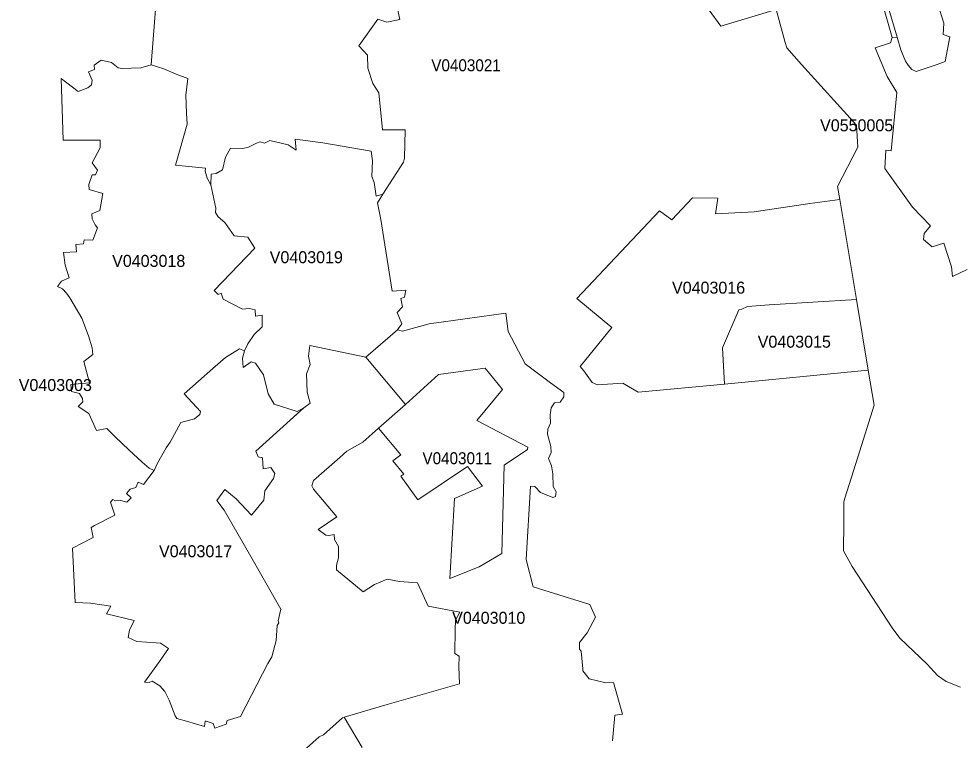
# Model space of a CAD drawing. Extents: x 369010 to 735936, y 6377141 to 6616555.
# Drawn here: x 425432 to 433279, y 6484437 to 6490450 of the extents above; entities that cross this region are included whole.
import ezdxf
from ezdxf.enums import TextEntityAlignment as Align

# ---------------------------------------------------------------- set-up
doc = ezdxf.new("R2010")
doc.units = 0
doc.header["$LTSCALE"] = 40
doc.layers.add('3', color=7, linetype='Continuous', lineweight=13)
doc.layers.add('4', color=7, linetype='Continuous')

msp = doc.modelspace()

# ---------------------------------------------------------------- linework, layer by layer
at = {"layer": '3'}
for points in [[(426643.33, 6491458.57), (426533.77, 6490066.35), (426639.19, 6490033.91), (426743.96, 6489988.9), (426840.12, 6489952.65), (426823.73, 6489813.79), (426829.36, 6489664.18), (426835.98, 6489571.83), (426736.84, 6489230.72), (426987.91, 6489205.07), (426984.27, 6489179.75), (427002.48, 6489120.83), (427031.44, 6489066.87), (427035.74, 6489155.42), (427077.62, 6489159.89), (427128.59, 6489192.16), (427153.91, 6489297.92), (427196.94, 6489370.74), (427300.05, 6489369.41), (427346.72, 6489379.18), (427412.6, 6489412.78), (427443.21, 6489424.53), (427478.8, 6489412.11), (427522.66, 6489436.11), (427675.91, 6489399.54), (427744.1, 6489355.18), (427736.32, 6489445.88), (427965.38, 6489415.59), (428368.22, 6489346.41), (428378.97, 6489265.64), (428374.34, 6489134.73), (428392.54, 6489085.91), (428410.75, 6488972.37), (428467.02, 6488988.75), (428637.99, 6489255.38), (428646.43, 6489287.82), (428651.23, 6489525.32), (428463.21, 6489524.33), (428433.26, 6489833.16), (428381.95, 6489910.94), (428339.58, 6490038.05), (428337.1, 6490146.46), (428266.93, 6490224.08), (428424.32, 6490446.85), (428498.3, 6490422.18), (428608.86, 6490444.03), (428543.32, 6490744.42)], [(426533.77, 6490066.35), (426643.33, 6491458.57)], [(428543.32, 6490744.42), (428608.86, 6490444.03), (428498.3, 6490422.18), (428424.32, 6490446.85), (428266.93, 6490224.08), (428337.1, 6490146.46), (428339.58, 6490038.05), (428381.95, 6489910.94), (428433.26, 6489833.16), (428463.21, 6489524.33), (428651.23, 6489525.32), (428646.43, 6489287.82), (428637.99, 6489255.38), (428467.02, 6488988.75), (428421.18, 6488917.26), (428450.14, 6488777.74), (428543.65, 6488180.6), (428657.52, 6488187.55), (428647.75, 6488128.47), (428614.65, 6488117.54), (428630.37, 6488048.69), (428585.52, 6488001.52), (428623.75, 6487906.86), (428588.17, 6487857.04), (428629.55, 6487847.27), (428853.31, 6487908.51), (429492.15, 6487996.56), (429510.19, 6487842.81), (429652.03, 6487574.69), (429864.37, 6487415.64), (429974.1, 6487335.2), (429974.1, 6487298.79), (429944.97, 6487255.76), (429897.64, 6487247.98), (429869.17, 6487207.77), (429860.07, 6487149.34), (429862.39, 6487079.83), (429841.7, 6487030.51), (429839.05, 6486988.47), (429865.36, 6486885.03), (429869.83, 6486835.71), (429847.82, 6486784.57), (429871.82, 6486723.83), (429884.23, 6486657.8), (429887.21, 6486551.71), (429910.55, 6486507.02), (429906.08, 6486468.79), (429883.74, 6486460.35), (429779.14, 6486501.89), (429731.8, 6486550.55), (429696.72, 6486553.2), (429661.79, 6485942.65), (429720.55, 6485714.75), (430191.08, 6485568.28), (430239.24, 6485463.19), (430168.9, 6485330.79), (430106.01, 6485251.67), (430106.01, 6485195.24), (430119.58, 6485179.68)], [(433090.21, 6490579.58), (433143.5, 6490412.92), (433138.04, 6490320.23), (433191.33, 6490298.72), (433152.94, 6490093), (433086.73, 6490068.34), (432910.8, 6490009.75), (432876.54, 6490027.62), (432844.11, 6490064.03), (432823.25, 6490096.47), (432784.85, 6490190.48), (432753.08, 6490297.56), (432712.7, 6490293.59), (432698.46, 6490250.72), (432570.86, 6490208.52), (432670.66, 6489969.2), (432749.77, 6489836.8), (432702.1, 6489349.39), (432658.58, 6489353.86), (432649.8, 6489202.26), (432881.84, 6488880.52), (433031.62, 6488725.27), (432977.67, 6488659.07), (432973.86, 6488609.75), (433044.37, 6488550.5), (433141.68, 6488580.95), (433207.72, 6488382.02), (433215, 6488302.91), (433337.8, 6488359.51)], [(432684.39, 6490529.1), (432753.08, 6490297.56), (432784.85, 6490190.48), (432823.25, 6490096.47), (432844.11, 6490064.03), (432876.54, 6490027.62), (432910.8, 6490009.75), (433086.73, 6490068.34), (433152.94, 6490093), (433191.33, 6490298.72), (433138.04, 6490320.23), (433143.5, 6490412.92), (433090.21, 6490579.58)], [(430141.92, 6487515.6), (430110.64, 6487550.53), (430374.12, 6487878.22), (430082.01, 6488118.2), (430773.15, 6488848.9), (430876.43, 6488773.77), (431046.4, 6488956.65), (431259.74, 6488954.83), (431239.71, 6488824.41), (431561.78, 6488840.79), (432024.53, 6488909.81), (432275.27, 6488944.57), (432257.39, 6489051.32), (432426.04, 6489381.16), (432415.78, 6489562.23), (431955.51, 6490069.33), (431834.37, 6490207.86), (431820.13, 6490253.37), (431745.82, 6490526.12)], [(431745.82, 6490526.12), (431284.23, 6490389.75), (431186.09, 6490521.98)], [(431186.09, 6490521.98), (431284.23, 6490389.75), (431745.82, 6490526.12)], [(431745.82, 6490526.12), (431820.13, 6490253.37), (431834.37, 6490207.86), (431955.51, 6490069.33), (432415.78, 6489562.23), (432426.04, 6489381.16), (432257.39, 6489051.32), (432275.27, 6488944.57), (432413.79, 6488111.09), (432512.1, 6487519.91), (432560.6, 6487229.28), (432426.7, 6486795.99), (432316.31, 6486454.23), (432308.37, 6486422.78), (432310.02, 6486251.48), (432306.88, 6486014.48), (432379.7, 6485884.07), (432710.71, 6485372.82), (432774.92, 6485287.75), (433003.98, 6485069.95), (433089.71, 6484976.44), (433162.2, 6484926.96), (433280.21, 6484879.13)], [(433337.8, 6488359.51), (433215, 6488302.91), (433207.72, 6488382.02), (433141.68, 6488580.95), (433044.37, 6488550.5), (432973.86, 6488609.75), (432977.67, 6488659.07), (433031.62, 6488725.27), (432881.84, 6488880.52), (432649.8, 6489202.26), (432658.58, 6489353.86), (432702.1, 6489349.39), (432749.77, 6489836.8), (432670.66, 6489969.2), (432570.86, 6490208.52), (432698.46, 6490250.72), (432712.7, 6490293.59), (432643.85, 6490526.45)], [(432643.85, 6490526.45), (432712.7, 6490293.59), (432753.08, 6490297.56), (432684.39, 6490529.1)], [(426560.25, 6486684.28), (426588.22, 6486746.34), (426661.04, 6486874.28), (426691.83, 6486921.44), (426783.02, 6487084.96), (426895.06, 6487116.74), (426941.57, 6487151.99), (426945.05, 6487175.49), (426809.17, 6487324.45), (427047.99, 6487535.8), (427154.74, 6487626.66), (427271.59, 6487700.31), (427311.97, 6487682.76), (427341.26, 6487740.19), (427393.23, 6487817.98), (427460.92, 6487883.68), (427459.76, 6487978.35), (427403.82, 6487970.57), (427401.34, 6488025.03), (427352.02, 6488035.45), (427297.4, 6488029), (427134.38, 6488112.74), (427117.5, 6488163.39), (427094.17, 6488151.8), (427060.4, 6488184.07), (427399.02, 6488539.08), (427339.28, 6488630.6), (427228.06, 6488640.04), (427149.61, 6488750.93), (427092.51, 6488798.92), (427071.16, 6488836.49), (427072.82, 6488871.08), (427031.44, 6489066.87), (427002.48, 6489120.83), (426984.27, 6489179.75), (426987.91, 6489205.07), (426736.84, 6489230.72), (426835.98, 6489571.83), (426829.36, 6489664.18), (426823.73, 6489813.79), (426840.12, 6489952.65), (426743.96, 6489988.9), (426639.19, 6490033.91), (426533.77, 6490066.35), (426447.71, 6490042.19), (426292.96, 6490034.41), (426259.69, 6490041.03), (426203.26, 6490086.87), (426117.53, 6490106.07), (426058.61, 6490064.2), (426061.09, 6490026.96), (426013.26, 6490007.93), (426042.72, 6489937.92), (426037.59, 6489899.19), (426006.14, 6489874.37), (425927.53, 6489843.25), (425784.7, 6489951.82), (425802.24, 6489437.27), (426110.74, 6489439.26), (426108.75, 6489375.04), (426041.73, 6489250.75), (426086.25, 6489189.35), (426071.19, 6489148.63), (426042.39, 6489148.63), (426015.74, 6489068.69), (426017.73, 6489028.14), (426130.6, 6488993.22), (426107.1, 6488851.72), (426040.24, 6488824.74), (426042.88, 6488781.54), (426067.05, 6488733.22), (426086.74, 6488708.23), (426048.51, 6488605.12), (425975.19, 6488607.76), (425970.56, 6488573.01), (425905.85, 6488568.21), (425912.3, 6488508.63), (425803.57, 6488502.67), (425818.79, 6488395.75), (425850.9, 6488290.33), (425787.35, 6488263.19), (425755.24, 6488218), (425794.63, 6488199.63), (425829.88, 6488164.38), (425856.2, 6488124.99), (425956.66, 6487955.84), (426012.27, 6487806.06), (426042.06, 6487707.75), (426048.18, 6487651.98), (425974.2, 6487594.38), (426021.7, 6487414.98), (425863.97, 6487402.23), (425871.92, 6487343.31), (425938.62, 6487325.61), (425963.61, 6487285.72), (425964.6, 6487257.58), (425925.38, 6487218.86), (426014.42, 6487158.78), (426079.29, 6487018.93), (426166.35, 6487034.65)], [(426979.8, 6484551.26), (426830.35, 6484594.95), (426749.92, 6484617.3), (426733.7, 6484639.48), (426685.04, 6484771.71), (426649.79, 6484842.22), (426607.25, 6484889.22), (426544.36, 6484929.27), (426518.21, 6484918.85), (426480.31, 6484921.49), (426605.6, 6485091.96), (426679.08, 6485200.7), (426613.05, 6485245.88), (426577.46, 6485247.54), (426415.27, 6485258.96), (426341.95, 6485291.73), (426353.7, 6485353.29), (426392.59, 6485435.88), (426163.7, 6485488.84), (426197.63, 6485553.55), (426028.82, 6485578.21), (425900.05, 6485585.99), (425879.7, 6486037.82), (426050.83, 6486125.7), (426034.44, 6486210.77), (426062.58, 6486226.49), (426232.72, 6486313.88), (426195.48, 6486421.79), (426215.01, 6486444.13), (426235.37, 6486432.38), (426283.2, 6486435.69), (426331.19, 6486421.95), (426367.27, 6486456.05), (426329.37, 6486491.96), (426360.65, 6486528.04), (426406.17, 6486542.94), (426427.02, 6486587.46), (426470.38, 6486568.42), (426560.25, 6486684.28), (426516.89, 6486703.31), (426458.46, 6486754.95), (426349.56, 6486855.9), (426235.53, 6486965.14), (426166.35, 6487034.65), (426079.29, 6487018.93), (426014.42, 6487158.78), (425925.38, 6487218.86), (425964.6, 6487257.58), (425963.61, 6487285.72), (425938.62, 6487325.61), (425871.92, 6487343.31), (425863.97, 6487402.23), (426021.7, 6487414.98), (425974.2, 6487594.38), (426048.18, 6487651.98), (426042.06, 6487707.75), (426012.27, 6487806.06), (425956.66, 6487955.84), (425856.2, 6488124.99), (425829.88, 6488164.38), (425794.63, 6488199.63), (425755.24, 6488218), (425787.35, 6488263.19), (425850.9, 6488290.33), (425818.79, 6488395.75), (425803.57, 6488502.67), (425912.3, 6488508.63), (425905.85, 6488568.21), (425970.56, 6488573.01), (425975.19, 6488607.76), (426048.51, 6488605.12), (426086.74, 6488708.23), (426067.05, 6488733.22), (426042.88, 6488781.54), (426040.24, 6488824.74), (426107.1, 6488851.72), (426130.6, 6488993.22), (426017.73, 6489028.14), (426015.74, 6489068.69), (426042.39, 6489148.63), (426071.19, 6489148.63), (426086.25, 6489189.35), (426041.73, 6489250.75), (426108.75, 6489375.04), (426110.74, 6489439.26), (425802.24, 6489437.27), (425784.7, 6489951.82), (425927.53, 6489843.25), (426006.14, 6489874.37), (426037.59, 6489899.19), (426042.72, 6489937.92), (426013.26, 6490007.93), (426061.09, 6490026.96), (426058.61, 6490064.2), (426117.53, 6490106.07), (426203.26, 6490086.87), (426259.69, 6490041.03), (426292.96, 6490034.41), (426447.71, 6490042.19), (426533.77, 6490066.35)], [(430379.59, 6484432.6), (430400.11, 6484646.26), (430463.33, 6484654.04), (430390.18, 6484918.68), (430324.31, 6484914.21), (430186.61, 6484948.14), (430134.14, 6485014.34), (430132.49, 6485030.4), (430119.58, 6485179.68), (430106.01, 6485195.24), (430106.01, 6485251.67), (430168.9, 6485330.79), (430239.24, 6485463.19), (430191.08, 6485568.28), (429720.55, 6485714.75), (429661.79, 6485942.65), (429696.72, 6486553.2), (429731.8, 6486550.55), (429779.14, 6486501.89), (429883.74, 6486460.35), (429906.08, 6486468.79), (429910.55, 6486507.02), (429887.21, 6486551.71), (429884.23, 6486657.8), (429871.82, 6486723.83), (429847.82, 6486784.57), (429869.83, 6486835.71), (429865.36, 6486885.03), (429839.05, 6486988.47), (429841.7, 6487030.51), (429862.39, 6487079.83), (429860.07, 6487149.34), (429869.17, 6487207.77), (429897.64, 6487247.98), (429944.97, 6487255.76), (429974.1, 6487298.79), (429974.1, 6487335.2), (429864.37, 6487415.64), (429652.03, 6487574.69), (429510.19, 6487842.81), (429492.15, 6487996.56), (428853.31, 6487908.51), (428629.55, 6487847.27), (428588.17, 6487857.04)], [(428588.17, 6487857.04), (428325.18, 6487629.97), (428654.21, 6487234.41), (428931.26, 6487485.15), (429318.21, 6487537.12), (429464.51, 6487359.04), (429248.7, 6487101.68), (429675.2, 6486880.73), (429671.89, 6486861.2), (429476.43, 6486728.14), (429458.89, 6485992.97), (429269.55, 6485882.74), (429023.61, 6485785.26), (429063.99, 6486451.74), (429296.86, 6486555.02), (429172.23, 6486719.36), (428758.31, 6486439.99), (428616.8, 6486636.94), (428640.8, 6486653.66), (428549.94, 6486765.87), (428615.31, 6486816.35), (428430.78, 6487036.64), (428299.03, 6486920.12), (428166.13, 6486847.13), (428107.22, 6486794.17), (427886.76, 6486600.53), (427873.85, 6486558.33), (427889.41, 6486529.7), (428083.71, 6486297.49), (427928.14, 6486192.73), (427989.54, 6486146.22), (428016.85, 6486143.58), (428059.72, 6486150.86), (428062.2, 6486111.14), (428095.96, 6486050.23), (428097.12, 6485957.22), (428078.91, 6485895.65), (428080.24, 6485857.25), (428301.85, 6485673.05), (428397.01, 6485735.44), (428501.78, 6485779.8), (428604.22, 6485760.1), (428755.99, 6485748.35), (428844.2, 6485554.22), (429109.01, 6485505.23), (429070.78, 6485437.37), (429068.79, 6485358.26), (429066.64, 6485159.99), (429102.39, 6485137.31), (429099.74, 6485048.44), (429105.7, 6484906.43), (428501.28, 6484734.31), (428143.96, 6484628.88), (428294.57, 6484376.99)], [(427830.66, 6484371.69), (427935.26, 6484465.37), (427971.17, 6484482.91), (428128.9, 6484624.41), (428143.96, 6484628.88), (428501.28, 6484734.31), (429105.7, 6484906.43), (429099.74, 6485048.44), (429102.39, 6485137.31), (429066.64, 6485159.99), (429068.79, 6485358.26), (429070.78, 6485437.37), (429109.01, 6485505.23), (428844.2, 6485554.22), (428755.99, 6485748.35), (428604.22, 6485760.1), (428501.78, 6485779.8), (428397.01, 6485735.44), (428301.85, 6485673.05), (428080.24, 6485857.25), (428078.91, 6485895.65), (428097.12, 6485957.22), (428095.96, 6486050.23), (428062.2, 6486111.14), (428059.72, 6486150.86), (428016.85, 6486143.58), (427989.54, 6486146.22), (427928.14, 6486192.73), (428083.71, 6486297.49), (427889.41, 6486529.7), (427873.85, 6486558.33), (427886.76, 6486600.53), (428107.22, 6486794.17), (428166.13, 6486847.13), (428299.03, 6486920.12), (428430.78, 6487036.64), (428654.21, 6487234.41), (428325.18, 6487629.97), (427856.64, 6487727.28), (427846.22, 6487637.08), (427861.28, 6487569.23), (427829.5, 6487489.45), (427835.95, 6487337.52), (427860.61, 6487247.32), (427807.16, 6487207.44), (427407.8, 6486844.98), (427427.32, 6486799.47), (427462.91, 6486789.21), (427468.2, 6486697.68), (427532.92, 6486711.09), (427565.36, 6486659.12), (427554.27, 6486618.9), (427483.1, 6486514.14), (427474.66, 6486436.35), (427371.55, 6486313.05), (427243.78, 6486447.44), (427149.77, 6486525.39), (427081.26, 6486434.2), (427143.15, 6486354.1), (427366.58, 6485966.82), (427616.99, 6485529.56), (427592.33, 6485432.9), (427597.79, 6485415.85), (427585.55, 6485392.52), (427575.78, 6485266.74), (427541.36, 6485132.51), (427506.27, 6485076.74), (427278.37, 6484634.01), (427168.81, 6484600.09), (427159.7, 6484569.96), (427064.87, 6484536.2), (427051.8, 6484575.59), (426992.21, 6484594.29), (426986.26, 6484594.95), (426979.8, 6484551.26)], [(433280.21, 6484879.13), (433162.2, 6484926.96), (433089.71, 6484976.44), (433003.98, 6485069.95), (432774.92, 6485287.75), (432710.71, 6485372.82), (432379.7, 6485884.07), (432306.88, 6486014.48), (432310.02, 6486251.48), (432308.37, 6486422.78), (432316.31, 6486454.23), (432426.7, 6486795.99), (432560.6, 6487229.28), (432512.1, 6487519.91), (431315.34, 6487404.88), (431313.69, 6487404.72), (430594.91, 6487337.19), (430465.81, 6487413.82), (430254.13, 6487398.59), (430210.61, 6487419.61), (430141.92, 6487515.6)], [(426166.35, 6487034.65), (426235.53, 6486965.14), (426349.56, 6486855.9), (426458.46, 6486754.95), (426516.89, 6486703.31), (426560.25, 6486684.28)], [(430119.58, 6485179.68), (430132.49, 6485030.4), (430134.14, 6485014.34), (430186.61, 6484948.14), (430324.31, 6484914.21), (430390.18, 6484918.68), (430463.33, 6484654.04), (430400.11, 6484646.26), (430379.59, 6484432.6)], [(428294.57, 6484376.99), (428143.96, 6484628.88), (428128.9, 6484624.41), (427971.17, 6484482.91), (427935.26, 6484465.37), (427830.66, 6484371.69)]]:
    msp.add_lwpolyline(points, dxfattribs=at)
for points in [[(427031.44, 6489066.87), (427072.82, 6488871.08), (427071.16, 6488836.49), (427092.51, 6488798.92), (427149.61, 6488750.93), (427228.06, 6488640.04), (427339.28, 6488630.6), (427399.02, 6488539.08), (427060.4, 6488184.07), (427094.17, 6488151.8), (427117.5, 6488163.39), (427134.38, 6488112.74), (427297.4, 6488029), (427352.02, 6488035.45), (427401.34, 6488025.03), (427403.82, 6487970.57), (427459.76, 6487978.35), (427460.92, 6487883.68), (427393.23, 6487817.98), (427341.26, 6487740.19), (427311.97, 6487682.76), (427297.07, 6487622.35), (427301.21, 6487542.91), (427368.07, 6487589.75), (427403.82, 6487579.32), (427471.35, 6487481.34), (427511.07, 6487322.96), (427558.9, 6487236.56), (427751.22, 6487177.48), (427807.16, 6487207.44), (427860.61, 6487247.32), (427835.95, 6487337.52), (427829.5, 6487489.45), (427861.28, 6487569.23), (427846.22, 6487637.08), (427856.64, 6487727.28), (428325.18, 6487629.97), (428588.17, 6487857.04), (428623.75, 6487906.86), (428585.52, 6488001.52), (428630.37, 6488048.69), (428614.65, 6488117.54), (428647.75, 6488128.47), (428657.52, 6488187.55), (428543.65, 6488180.6), (428450.14, 6488777.74), (428421.18, 6488917.26), (428467.02, 6488988.75), (428410.75, 6488972.37), (428392.54, 6489085.91), (428374.34, 6489134.73), (428378.97, 6489265.64), (428368.22, 6489346.41), (427965.38, 6489415.59), (427736.32, 6489445.88), (427744.1, 6489355.18), (427675.91, 6489399.54), (427522.66, 6489436.11), (427478.8, 6489412.11), (427443.21, 6489424.53), (427412.6, 6489412.78), (427346.72, 6489379.18), (427300.05, 6489369.41), (427196.94, 6489370.74), (427153.91, 6489297.92), (427128.59, 6489192.16), (427077.62, 6489159.89), (427035.74, 6489155.42)], [(431313.69, 6487404.72), (431297.47, 6487707.26), (431433.51, 6488023.2), (431457.51, 6488028.34), (431504.85, 6488051.67), (431685.91, 6488066.73), (432413.79, 6488111.09), (432275.27, 6488944.57), (432024.53, 6488909.81), (431561.78, 6488840.79), (431239.71, 6488824.41), (431259.74, 6488954.83), (431046.4, 6488956.65), (430876.43, 6488773.77), (430773.15, 6488848.9), (430082.01, 6488118.2), (430374.12, 6487878.22), (430110.64, 6487550.53), (430141.92, 6487515.6), (430210.61, 6487419.61), (430254.13, 6487398.59), (430465.81, 6487413.82), (430594.91, 6487337.19)], [(432413.79, 6488111.09), (431685.91, 6488066.73), (431504.85, 6488051.67), (431457.51, 6488028.34), (431433.51, 6488023.2), (431297.47, 6487707.26), (431313.69, 6487404.72), (431315.34, 6487404.88), (432512.1, 6487519.91)], [(426560.25, 6486684.28), (426470.38, 6486568.42), (426427.02, 6486587.46), (426406.17, 6486542.94), (426360.65, 6486528.04), (426329.37, 6486491.96), (426367.27, 6486456.05), (426331.19, 6486421.95), (426283.2, 6486435.69), (426235.37, 6486432.38), (426215.01, 6486444.13), (426195.48, 6486421.79), (426232.72, 6486313.88), (426062.58, 6486226.49), (426034.44, 6486210.77), (426050.83, 6486125.7), (425879.7, 6486037.82), (425900.05, 6485585.99), (426028.82, 6485578.21), (426197.63, 6485553.55), (426163.7, 6485488.84), (426392.59, 6485435.88), (426353.7, 6485353.29), (426341.95, 6485291.73), (426415.27, 6485258.96), (426577.46, 6485247.54), (426613.05, 6485245.88), (426679.08, 6485200.7), (426605.6, 6485091.96), (426480.31, 6484921.49), (426518.21, 6484918.85), (426544.36, 6484929.27), (426607.25, 6484889.22), (426649.79, 6484842.22), (426685.04, 6484771.71), (426733.7, 6484639.48), (426749.92, 6484617.3), (426830.35, 6484594.95), (426979.8, 6484551.26), (426986.26, 6484594.95), (426992.21, 6484594.29), (427051.8, 6484575.59), (427064.87, 6484536.2), (427159.7, 6484569.96), (427168.81, 6484600.09), (427278.37, 6484634.01), (427506.27, 6485076.74), (427541.36, 6485132.51), (427575.78, 6485266.74), (427585.55, 6485392.52), (427597.79, 6485415.85), (427592.33, 6485432.9), (427616.99, 6485529.56), (427366.58, 6485966.82), (427143.15, 6486354.1), (427081.26, 6486434.2), (427149.77, 6486525.39), (427243.78, 6486447.44), (427371.55, 6486313.05), (427474.66, 6486436.35), (427483.1, 6486514.14), (427554.27, 6486618.9), (427565.36, 6486659.12), (427532.92, 6486711.09), (427468.2, 6486697.68), (427462.91, 6486789.21), (427427.32, 6486799.47), (427407.8, 6486844.98), (427807.16, 6487207.44), (427751.22, 6487177.48), (427558.9, 6487236.56), (427511.07, 6487322.96), (427471.35, 6487481.34), (427403.82, 6487579.32), (427368.07, 6487589.75), (427301.21, 6487542.91), (427297.07, 6487622.35), (427311.97, 6487682.76), (427271.59, 6487700.31), (427154.74, 6487626.66), (427047.99, 6487535.8), (426809.17, 6487324.45), (426945.05, 6487175.49), (426941.57, 6487151.99), (426895.06, 6487116.74), (426783.02, 6487084.96), (426691.83, 6486921.44), (426661.04, 6486874.28), (426588.22, 6486746.34)], [(428654.21, 6487234.41), (428430.78, 6487036.64), (428615.31, 6486816.35), (428549.94, 6486765.87), (428640.8, 6486653.66), (428616.8, 6486636.94), (428758.31, 6486439.99), (429172.23, 6486719.36), (429296.86, 6486555.02), (429063.99, 6486451.74), (429023.61, 6485785.26), (429269.55, 6485882.74), (429458.89, 6485992.97), (429476.43, 6486728.14), (429671.89, 6486861.2), (429675.2, 6486880.73), (429248.7, 6487101.68), (429464.51, 6487359.04), (429318.21, 6487537.12), (428931.26, 6487485.15)]]:
    msp.add_lwpolyline(points, close=True, dxfattribs=at)

# ---------------------------------------------------------------- texts
at = {"layer": '4', "width": 0.95}
for s, p in [('V0403021', (429159.57, 6490012.51)), ('V0403011', (429086.01, 6486737.05))]:
    msp.add_text(s, height=100, dxfattribs=at).set_placement(p, align=Align.CENTER)
at = {"layer": '4'}
for s, p in [('V0550005', (432415.78, 6489512.23)), ('V0403018', (426514.31, 6488382.1)), ('V0403019', (427827.98, 6488412.86)), ('V0403016', (431181.36, 6488159.05)), ('V0403015', (431895.98, 6487708.53)), ('V0403003', (425735.92, 6487347.38)), ('V0403017', (426905.09, 6485962)), ('V0403010', (429348.9, 6485407.07))]:
    msp.add_text(s, height=100, dxfattribs=at).set_placement(p, align=Align.CENTER)

doc.saveas('drawing.dxf')
